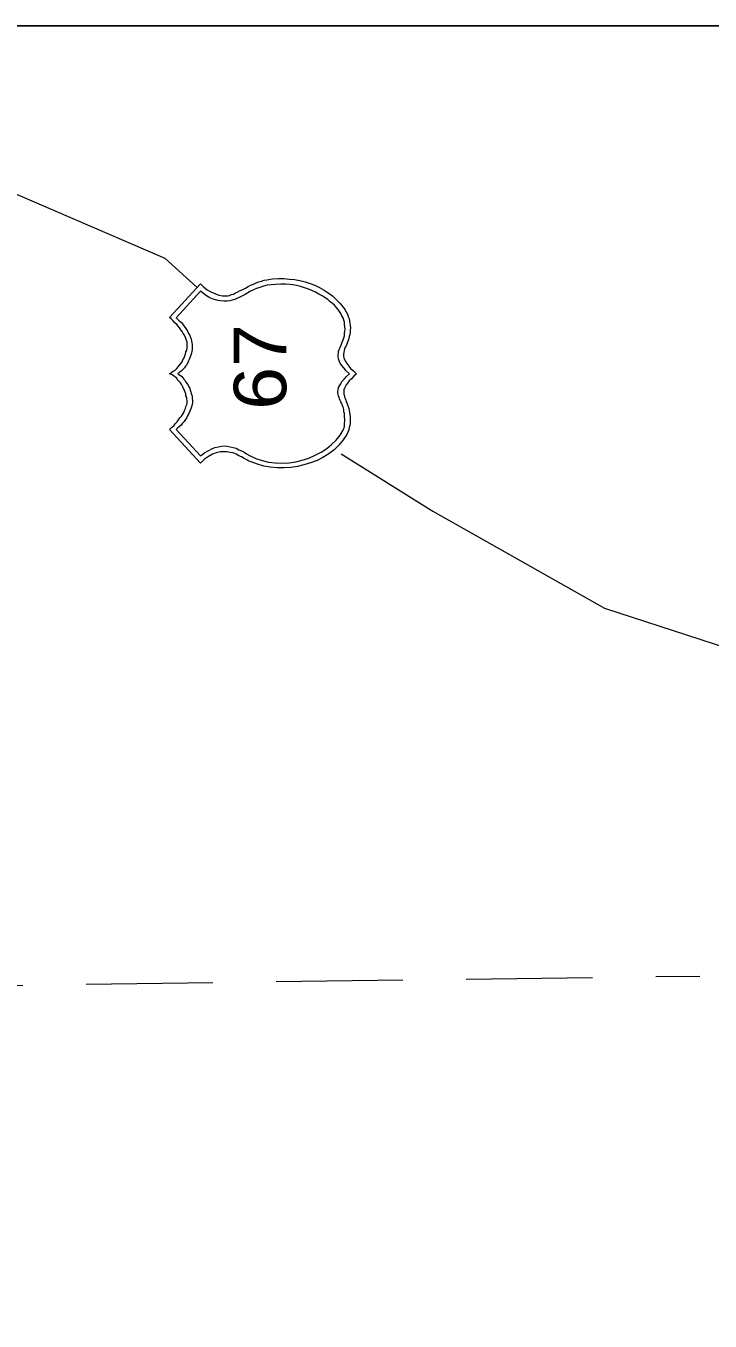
# Model space of a CAD drawing. Extents: x 2363323 to 2367082, y 6956018 to 6980837.
# Drawn here: x 2366064.3 to 2366130.8, y 6980709.7 to 6980835.5 of the extents above; entities that cross this region are included whole.
import ezdxf

# ---------------------------------------------------------------- set-up
doc = ezdxf.new("R2010")
doc.units = 0
doc.header["$LTSCALE"] = 4.1
doc.linetypes.add('MEDIUM_DASHED', pattern=[4.5, 3, -1.5])
doc.layers.add('62', color=7, linetype='Continuous', lineweight=13)
doc.layers.add('63', color=7, linetype='Continuous', lineweight=13)

msp = doc.modelspace()

# ---------------------------------------------------------------- linework, layer by layer
at = {"layer": '62'}
msp.add_line((2366077.847, 6980812.974), (2366080.974, 6980810.118), dxfattribs=at)
at = {"layer": '62', "linetype": 'MEDIUM_DASHED'}
msp.add_line((2365848.822, 6980739.484), (2366129.802, 6980743.218), dxfattribs=at)
at = {"layer": '62', "lineweight": 25}
msp.add_lwpolyline([(2365753.976, 6980385.954), (2366219.249, 6980385.954), (2366219.249, 6980835.546), (2365753.974, 6980835.546)], dxfattribs=at)
at = {"layer": '62'}
for points in [[(2366041.328, 6980835.544), (2366046.682, 6980830.731), (2366061.803, 6980819.864), (2366077.847, 6980812.974)], [(2366081.312, 6980793.062), (2366078.298, 6980796.326), (2366078.5, 6980796.506), (2366078.704, 6980796.686), (2366078.86, 6980796.888), (2366079.04, 6980797.066), (2366079.176, 6980797.25), (2366079.31, 6980797.45), (2366079.446, 6980797.608), (2366079.581, 6980797.81), (2366079.692, 6980797.99), (2366079.76, 6980798.172), (2366079.85, 6980798.373), (2366079.894, 6980798.553), (2366079.962, 6980798.756), (2366080.008, 6980798.913), (2366080.008, 6980799.117), (2366079.983, 6980799.318), (2366079.964, 6980799.452), (2366079.896, 6980799.61), (2366079.872, 6980799.79), (2366079.827, 6980799.97), (2366079.738, 6980800.152), (2366079.67, 6980800.308), (2366079.581, 6980800.488), (2366079.491, 6980800.668), (2366079.356, 6980800.848), (2366079.244, 6980801.006), (2366079.084, 6980801.163), (2366078.994, 6980801.32), (2366078.814, 6980801.456), (2366078.657, 6980801.568), (2366078.477, 6980801.658), (2366078.296, 6980801.748), (2366078.477, 6980801.86), (2366078.657, 6980801.997), (2366078.837, 6980802.108), (2366078.994, 6980802.266), (2366079.152, 6980802.4), (2366079.266, 6980802.58), (2366079.401, 6980802.738), (2366079.512, 6980802.918), (2366079.604, 6980803.098), (2366079.716, 6980803.278), (2366079.784, 6980803.48), (2366079.851, 6980803.66), (2366079.894, 6980803.886), (2366079.964, 6980804.043), (2366080.008, 6980804.268), (2366080.008, 6980804.47), (2366080.008, 6980804.628), (2366080.008, 6980804.808), (2366079.941, 6980804.964), (2366079.896, 6980805.168), (2366079.806, 6980805.326), (2366079.737, 6980805.506), (2366079.626, 6980805.663), (2366079.536, 6980805.843), (2366079.401, 6980806.002), (2366079.266, 6980806.204), (2366079.131, 6980806.36), (2366078.996, 6980806.542), (2366078.816, 6980806.698), (2366078.657, 6980806.9), (2366078.477, 6980807.037), (2366078.298, 6980807.216), (2366081.314, 6980810.478), (2366081.603, 6980810.186), (2366081.942, 6980809.893), (2366082.324, 6980809.69), (2366082.707, 6980809.533), (2366083.09, 6980809.377), (2366083.45, 6980809.33), (2366083.742, 6980809.31), (2366083.946, 6980809.33), (2366084.126, 6980809.354), (2366084.304, 6980809.443), (2366084.508, 6980809.488), (2366084.711, 6980809.6), (2366084.934, 6980809.712), (2366085.161, 6980809.827), (2366085.408, 6980809.938), (2366085.677, 6980810.073), (2366085.924, 6980810.21), (2366086.172, 6980810.344), (2366086.464, 6980810.456), (2366086.712, 6980810.568), (2366086.984, 6980810.68), (2366087.231, 6980810.748), (2366087.477, 6980810.84), (2366087.747, 6980810.862), (2366088.31, 6980810.952), (2366088.874, 6980810.997), (2366089.391, 6980810.996), (2366089.93, 6980810.95), (2366090.446, 6980810.904), (2366090.964, 6980810.793), (2366091.46, 6980810.68), (2366091.956, 6980810.523), (2366092.427, 6980810.343), (2366092.878, 6980810.12)], [(2366093.666, 6980808.948), (2366093.418, 6980809.126), (2366093.124, 6980809.33), (2366092.81, 6980809.488), (2366092.472, 6980809.67), (2366092.112, 6980809.824), (2366091.73, 6980809.983), (2366091.323, 6980810.14), (2366090.92, 6980810.253), (2366090.47, 6980810.343), (2366090.02, 6980810.41), (2366089.571, 6980810.456), (2366089.098, 6980810.456), (2366088.602, 6980810.433), (2366088.174, 6980810.388), (2366087.77, 6980810.342), (2366087.41, 6980810.253), (2366087.072, 6980810.139), (2366086.758, 6980810.028), (2366086.442, 6980809.893), (2366086.172, 6980809.76), (2366085.904, 6980809.6), (2366085.632, 6980809.443), (2366085.386, 6980809.33), (2366085.138, 6980809.196), (2366084.891, 6980809.083), (2366084.644, 6980808.972), (2366084.394, 6980808.903), (2366084.17, 6980808.836), (2366083.9, 6980808.79), (2366083.584, 6980808.789), (2366083.226, 6980808.834), (2366082.887, 6980808.903), (2366082.551, 6980808.992), (2366082.214, 6980809.128), (2366081.898, 6980809.33), (2366081.604, 6980809.534), (2366081.312, 6980809.756), (2366078.928, 6980807.193), (2366079.084, 6980807.036), (2366079.244, 6980806.9), (2366079.424, 6980806.743), (2366079.558, 6980806.587), (2366079.694, 6980806.406), (2366079.827, 6980806.226), (2366079.941, 6980806.047), (2366080.052, 6980805.866), (2366080.142, 6980805.663), (2366080.254, 6980805.483), (2366080.344, 6980805.28), (2366080.39, 6980805.123), (2366080.434, 6980804.922), (2366080.458, 6980804.763), (2366080.502, 6980804.628), (2366080.504, 6980804.47), (2366080.504, 6980804.312), (2366080.48, 6980804.11), (2366080.457, 6980803.932), (2366080.434, 6980803.75), (2366080.368, 6980803.546), (2366080.3, 6980803.39), (2366080.232, 6980803.188), (2366080.142, 6980803.008), (2366080.074, 6980802.85), (2366079.962, 6980802.626), (2366079.85, 6980802.49), (2366079.737, 6980802.333), (2366079.604, 6980802.153), (2366079.446, 6980802.04), (2366079.31, 6980801.883), (2366079.107, 6980801.75), (2366079.287, 6980801.613), (2366079.446, 6980801.502), (2366079.58, 6980801.343), (2366079.692, 6980801.208), (2366079.806, 6980801.072), (2366079.896, 6980800.938), (2366080.007, 6980800.76), (2366080.12, 6980800.647), (2366080.163, 6980800.466), (2366080.254, 6980800.31), (2366080.301, 6980800.15), (2366080.367, 6980799.993), (2366080.39, 6980799.836), (2366080.457, 6980799.656), (2366080.48, 6980799.5), (2366080.504, 6980799.34), (2366080.524, 6980799.16), (2366080.524, 6980798.936), (2366080.48, 6980798.757), (2366080.434, 6980798.53), (2366080.367, 6980798.328), (2366080.277, 6980798.102), (2366080.187, 6980797.88), (2366080.074, 6980797.72), (2366079.964, 6980797.496), (2366079.851, 6980797.293), (2366079.716, 6980797.113), (2366079.557, 6980796.956), (2366079.422, 6980796.754), (2366079.242, 6980796.596)], [(2366092.878, 6980810.12), (2366093.304, 6980809.87), (2366093.71, 6980809.6), (2366094.116, 6980809.31), (2366094.497, 6980808.95), (2366094.834, 6980808.588), (2366095.172, 6980808.206), (2366095.33, 6980807.98), (2366095.466, 6980807.756), (2366095.577, 6980807.53), (2366095.643, 6980807.306), (2366095.734, 6980807.103), (2366095.781, 6980806.878), (2366095.826, 6980806.63), (2366095.848, 6980806.43), (2366095.871, 6980806.203), (2366095.847, 6980805.978), (2366095.847, 6980805.777), (2366095.804, 6980805.574), (2366095.734, 6980805.35), (2366095.712, 6980805.168), (2366095.644, 6980804.99), (2366095.578, 6980804.808), (2366095.51, 6980804.628), (2366095.442, 6980804.47), (2366095.35, 6980804.313), (2366095.308, 6980804.154), (2366095.262, 6980803.998), (2366095.217, 6980803.818), (2366095.196, 6980803.659), (2366095.196, 6980803.48), (2366095.241, 6980803.299), (2366095.308, 6980803.12), (2366095.42, 6980802.918), (2366095.532, 6980802.738), (2366095.714, 6980802.49), (2366095.89, 6980802.266), (2366096.164, 6980802.04), (2366096.456, 6980801.748), (2366096.186, 6980801.5), (2366095.96, 6980801.253), (2366095.734, 6980801.052), (2366095.601, 6980800.848), (2366095.466, 6980800.668), (2366095.352, 6980800.488), (2366095.308, 6980800.33), (2366095.24, 6980800.173), (2366095.218, 6980800.036), (2366095.217, 6980799.88), (2366095.24, 6980799.766), (2366095.284, 6980799.61), (2366095.307, 6980799.476), (2366095.352, 6980799.34), (2366095.42, 6980799.183), (2366095.464, 6980799.026), (2366095.534, 6980798.913), (2366095.577, 6980798.733), (2366095.646, 6980798.553), (2366095.712, 6980798.374), (2366095.736, 6980798.17), (2366095.781, 6980797.992), (2366095.824, 6980797.766), (2366095.847, 6980797.586), (2366095.847, 6980797.36), (2366095.847, 6980797.18), (2366095.848, 6980796.956), (2366095.824, 6980796.708), (2366095.757, 6980796.506), (2366095.712, 6980796.28), (2366095.624, 6980796.056), (2366095.508, 6980795.83), (2366095.172, 6980795.314), (2366094.744, 6980794.816), (2366094.274, 6980794.366), (2366093.756, 6980793.962), (2366093.192, 6980793.602), (2366092.631, 6980793.31), (2366092.001, 6980793.084), (2366091.347, 6980792.882), (2366090.717, 6980792.746), (2366090.064, 6980792.632), (2366089.39, 6980792.589), (2366088.737, 6980792.589), (2366088.064, 6980792.655), (2366087.454, 6980792.769), (2366086.826, 6980792.949), (2366086.24, 6980793.174), (2366086.016, 6980793.262), (2366085.79, 6980793.376), (2366085.542, 6980793.512), (2366085.294, 6980793.669), (2366085.026, 6980793.782), (2366084.756, 6980793.916), (2366084.464, 6980794.053), (2366084.171, 6980794.096), (2366083.854, 6980794.164), (2366083.518, 6980794.164), (2366083.202, 6980794.164), (2366082.842, 6980794.052), (2366082.482, 6980793.938), (2366082.077, 6980793.714)], [(2366078.951, 6980796.327), (2366081.312, 6980793.759), (2366081.694, 6980794.052), (2366082.054, 6980794.254), (2366082.392, 6980794.434), (2366082.707, 6980794.569), (2366083.044, 6980794.638), (2366083.338, 6980794.704), (2366083.607, 6980794.749), (2366083.901, 6980794.706), (2366084.192, 6980794.638), (2366084.464, 6980794.592), (2366084.756, 6980794.502), (2366085.024, 6980794.366), (2366085.272, 6980794.256), (2366085.544, 6980794.119), (2366085.788, 6980793.962), (2366086.06, 6980793.806), (2366086.667, 6980793.512), (2366087.298, 6980793.309), (2366087.904, 6980793.152), (2366088.557, 6980793.084), (2366089.234, 6980793.062), (2366089.907, 6980793.084), (2366090.56, 6980793.196), (2366091.191, 6980793.354), (2366091.844, 6980793.556), (2366092.45, 6980793.826), (2366093.036, 6980794.119), (2366093.574, 6980794.479), (2366094.024, 6980794.863), (2366094.498, 6980795.29), (2366094.857, 6980795.762), (2366095.172, 6980796.258), (2366095.194, 6980796.37), (2366095.262, 6980796.484), (2366095.308, 6980796.64), (2366095.307, 6980796.822), (2366095.307, 6980796.956), (2366095.33, 6980797.137), (2366095.33, 6980797.316), (2366095.308, 6980797.496), (2366095.307, 6980797.698), (2366095.308, 6980797.878), (2366095.24, 6980798.058), (2366095.217, 6980798.238), (2366095.194, 6980798.418), (2366095.127, 6980798.576), (2366095.082, 6980798.734), (2366095.037, 6980798.868), (2366094.948, 6980799.026), (2366094.88, 6980799.16), (2366094.812, 6980799.296), (2366094.768, 6980799.43), (2366094.701, 6980799.61), (2366094.678, 6980799.723), (2366094.654, 6980799.88), (2366094.654, 6980800.038), (2366094.677, 6980800.197), (2366094.722, 6980800.42), (2366094.791, 6980800.578), (2366094.924, 6980800.76), (2366095.037, 6980800.983), (2366095.262, 6980801.21), (2366095.487, 6980801.478), (2366095.78, 6980801.726), (2366095.466, 6980802.04), (2366095.24, 6980802.312), (2366095.038, 6980802.537), (2366094.88, 6980802.783), (2366094.79, 6980803.01), (2366094.722, 6980803.188), (2366094.678, 6980803.39), (2366094.677, 6980803.593), (2366094.7, 6980803.773), (2366094.722, 6980803.932), (2366094.79, 6980804.11), (2366094.857, 6980804.292), (2366094.924, 6980804.47), (2366095.016, 6980804.628), (2366095.082, 6980804.829), (2366095.172, 6980805.033), (2366095.217, 6980805.236), (2366095.307, 6980805.438), (2366095.307, 6980805.664), (2366095.33, 6980805.866), (2366095.354, 6980806.09), (2366095.33, 6980806.316), (2366095.307, 6980806.518), (2366095.286, 6980806.743), (2366095.216, 6980806.944), (2366095.172, 6980807.172), (2366095.038, 6980807.374), (2366094.948, 6980807.598), (2366094.814, 6980807.78), (2366094.678, 6980808.003), (2366094.497, 6980808.206), (2366094.317, 6980808.408), (2366094.137, 6980808.564), (2366093.89, 6980808.746), (2366093.666, 6980808.948)], [(2366079.242, 6980796.596), (2366079.086, 6980796.46), (2366078.951, 6980796.327)], [(2366082.077, 6980793.714), (2366081.696, 6980793.444), (2366081.312, 6980793.062)], [(2366094.97, 6980793.962), (2366103.882, 6980788.406), (2366120.534, 6980778.952), (2366139.278, 6980772.878), (2366153.61, 6980769.728), (2366166.728, 6980753.031), (2366176.79, 6980752.894), (2366186.194, 6980736.56), (2366195.014, 6980723.396), (2366202.238, 6980707.329), (2366206.47, 6980684.916), (2366210.836, 6980665.836), (2366216.234, 6980645.043), (2366219.25, 6980632.51)]]:
    msp.add_lwpolyline(points, dxfattribs=at)
at = {"layer": '63'}
msp.add_line((2366077.847, 6980812.974), (2366080.974, 6980810.118), dxfattribs=at)
at = {"layer": '63', "linetype": 'MEDIUM_DASHED'}
msp.add_line((2365848.822, 6980739.484), (2366129.802, 6980743.218), dxfattribs=at)
at = {"layer": '63', "lineweight": 25}
msp.add_lwpolyline([(2365753.976, 6980385.954), (2366219.249, 6980385.954), (2366219.249, 6980835.546), (2365753.974, 6980835.546)], dxfattribs=at)
at = {"layer": '63'}
for points in [[(2366041.328, 6980835.544), (2366046.682, 6980830.731), (2366061.803, 6980819.864), (2366077.847, 6980812.974)], [(2366081.312, 6980793.062), (2366078.298, 6980796.326), (2366078.5, 6980796.506), (2366078.704, 6980796.686), (2366078.86, 6980796.888), (2366079.04, 6980797.066), (2366079.176, 6980797.25), (2366079.31, 6980797.45), (2366079.446, 6980797.608), (2366079.581, 6980797.81), (2366079.692, 6980797.99), (2366079.76, 6980798.172), (2366079.85, 6980798.373), (2366079.894, 6980798.553), (2366079.962, 6980798.756), (2366080.008, 6980798.913), (2366080.008, 6980799.117), (2366079.983, 6980799.318), (2366079.964, 6980799.452), (2366079.896, 6980799.61), (2366079.872, 6980799.79), (2366079.827, 6980799.97), (2366079.738, 6980800.152), (2366079.67, 6980800.308), (2366079.581, 6980800.488), (2366079.491, 6980800.668), (2366079.356, 6980800.848), (2366079.244, 6980801.006), (2366079.084, 6980801.163), (2366078.994, 6980801.32), (2366078.814, 6980801.456), (2366078.657, 6980801.568), (2366078.477, 6980801.658), (2366078.296, 6980801.748), (2366078.477, 6980801.86), (2366078.657, 6980801.997), (2366078.837, 6980802.108), (2366078.994, 6980802.266), (2366079.152, 6980802.4), (2366079.266, 6980802.58), (2366079.401, 6980802.738), (2366079.512, 6980802.918), (2366079.604, 6980803.098), (2366079.716, 6980803.278), (2366079.784, 6980803.48), (2366079.851, 6980803.66), (2366079.894, 6980803.886), (2366079.964, 6980804.043), (2366080.008, 6980804.268), (2366080.008, 6980804.47), (2366080.008, 6980804.628), (2366080.008, 6980804.808), (2366079.941, 6980804.964), (2366079.896, 6980805.168), (2366079.806, 6980805.326), (2366079.737, 6980805.506), (2366079.626, 6980805.663), (2366079.536, 6980805.843), (2366079.401, 6980806.002), (2366079.266, 6980806.204), (2366079.131, 6980806.36), (2366078.996, 6980806.542), (2366078.816, 6980806.698), (2366078.657, 6980806.9), (2366078.477, 6980807.037), (2366078.298, 6980807.216), (2366081.314, 6980810.478), (2366081.603, 6980810.186), (2366081.942, 6980809.893), (2366082.324, 6980809.69), (2366082.707, 6980809.533), (2366083.09, 6980809.377), (2366083.45, 6980809.33), (2366083.742, 6980809.31), (2366083.946, 6980809.33), (2366084.126, 6980809.354), (2366084.304, 6980809.443), (2366084.508, 6980809.488), (2366084.711, 6980809.6), (2366084.934, 6980809.712), (2366085.161, 6980809.827), (2366085.408, 6980809.938), (2366085.677, 6980810.073), (2366085.924, 6980810.21), (2366086.172, 6980810.344), (2366086.464, 6980810.456), (2366086.712, 6980810.568), (2366086.984, 6980810.68), (2366087.231, 6980810.748), (2366087.477, 6980810.84), (2366087.747, 6980810.862), (2366088.31, 6980810.952), (2366088.874, 6980810.997), (2366089.391, 6980810.996), (2366089.93, 6980810.95), (2366090.446, 6980810.904), (2366090.964, 6980810.793), (2366091.46, 6980810.68), (2366091.956, 6980810.523), (2366092.427, 6980810.343), (2366092.878, 6980810.12)], [(2366093.666, 6980808.948), (2366093.418, 6980809.126), (2366093.124, 6980809.33), (2366092.81, 6980809.488), (2366092.472, 6980809.67), (2366092.112, 6980809.824), (2366091.73, 6980809.983), (2366091.323, 6980810.14), (2366090.92, 6980810.253), (2366090.47, 6980810.343), (2366090.02, 6980810.41), (2366089.571, 6980810.456), (2366089.098, 6980810.456), (2366088.602, 6980810.433), (2366088.174, 6980810.388), (2366087.77, 6980810.342), (2366087.41, 6980810.253), (2366087.072, 6980810.139), (2366086.758, 6980810.028), (2366086.442, 6980809.893), (2366086.172, 6980809.76), (2366085.904, 6980809.6), (2366085.632, 6980809.443), (2366085.386, 6980809.33), (2366085.138, 6980809.196), (2366084.891, 6980809.083), (2366084.644, 6980808.972), (2366084.394, 6980808.903), (2366084.17, 6980808.836), (2366083.9, 6980808.79), (2366083.584, 6980808.789), (2366083.226, 6980808.834), (2366082.887, 6980808.903), (2366082.551, 6980808.992), (2366082.214, 6980809.128), (2366081.898, 6980809.33), (2366081.604, 6980809.534), (2366081.312, 6980809.756), (2366078.928, 6980807.193), (2366079.084, 6980807.036), (2366079.244, 6980806.9), (2366079.424, 6980806.743), (2366079.558, 6980806.587), (2366079.694, 6980806.406), (2366079.827, 6980806.226), (2366079.941, 6980806.047), (2366080.052, 6980805.866), (2366080.142, 6980805.663), (2366080.254, 6980805.483), (2366080.344, 6980805.28), (2366080.39, 6980805.123), (2366080.434, 6980804.922), (2366080.458, 6980804.763), (2366080.502, 6980804.628), (2366080.504, 6980804.47), (2366080.504, 6980804.312), (2366080.48, 6980804.11), (2366080.457, 6980803.932), (2366080.434, 6980803.75), (2366080.368, 6980803.546), (2366080.3, 6980803.39), (2366080.232, 6980803.188), (2366080.142, 6980803.008), (2366080.074, 6980802.85), (2366079.962, 6980802.626), (2366079.85, 6980802.49), (2366079.737, 6980802.333), (2366079.604, 6980802.153), (2366079.446, 6980802.04), (2366079.31, 6980801.883), (2366079.107, 6980801.75), (2366079.287, 6980801.613), (2366079.446, 6980801.502), (2366079.58, 6980801.343), (2366079.692, 6980801.208), (2366079.806, 6980801.072), (2366079.896, 6980800.938), (2366080.007, 6980800.76), (2366080.12, 6980800.647), (2366080.163, 6980800.466), (2366080.254, 6980800.31), (2366080.301, 6980800.15), (2366080.367, 6980799.993), (2366080.39, 6980799.836), (2366080.457, 6980799.656), (2366080.48, 6980799.5), (2366080.504, 6980799.34), (2366080.524, 6980799.16), (2366080.524, 6980798.936), (2366080.48, 6980798.757), (2366080.434, 6980798.53), (2366080.367, 6980798.328), (2366080.277, 6980798.102), (2366080.187, 6980797.88), (2366080.074, 6980797.72), (2366079.964, 6980797.496), (2366079.851, 6980797.293), (2366079.716, 6980797.113), (2366079.557, 6980796.956), (2366079.422, 6980796.754), (2366079.242, 6980796.596)], [(2366092.878, 6980810.12), (2366093.304, 6980809.87), (2366093.71, 6980809.6), (2366094.116, 6980809.31), (2366094.497, 6980808.95), (2366094.834, 6980808.588), (2366095.172, 6980808.206), (2366095.33, 6980807.98), (2366095.466, 6980807.756), (2366095.577, 6980807.53), (2366095.643, 6980807.306), (2366095.734, 6980807.103), (2366095.781, 6980806.878), (2366095.826, 6980806.63), (2366095.848, 6980806.43), (2366095.871, 6980806.203), (2366095.847, 6980805.978), (2366095.847, 6980805.777), (2366095.804, 6980805.574), (2366095.734, 6980805.35), (2366095.712, 6980805.168), (2366095.644, 6980804.99), (2366095.578, 6980804.808), (2366095.51, 6980804.628), (2366095.442, 6980804.47), (2366095.35, 6980804.313), (2366095.308, 6980804.154), (2366095.262, 6980803.998), (2366095.217, 6980803.818), (2366095.196, 6980803.659), (2366095.196, 6980803.48), (2366095.241, 6980803.299), (2366095.308, 6980803.12), (2366095.42, 6980802.918), (2366095.532, 6980802.738), (2366095.714, 6980802.49), (2366095.89, 6980802.266), (2366096.164, 6980802.04), (2366096.456, 6980801.748), (2366096.186, 6980801.5), (2366095.96, 6980801.253), (2366095.734, 6980801.052), (2366095.601, 6980800.848), (2366095.466, 6980800.668), (2366095.352, 6980800.488), (2366095.308, 6980800.33), (2366095.24, 6980800.173), (2366095.218, 6980800.036), (2366095.217, 6980799.88), (2366095.24, 6980799.766), (2366095.284, 6980799.61), (2366095.307, 6980799.476), (2366095.352, 6980799.34), (2366095.42, 6980799.183), (2366095.464, 6980799.026), (2366095.534, 6980798.913), (2366095.577, 6980798.733), (2366095.646, 6980798.553), (2366095.712, 6980798.374), (2366095.736, 6980798.17), (2366095.781, 6980797.992), (2366095.824, 6980797.766), (2366095.847, 6980797.586), (2366095.847, 6980797.36), (2366095.847, 6980797.18), (2366095.848, 6980796.956), (2366095.824, 6980796.708), (2366095.757, 6980796.506), (2366095.712, 6980796.28), (2366095.624, 6980796.056), (2366095.508, 6980795.83), (2366095.172, 6980795.314), (2366094.744, 6980794.816), (2366094.274, 6980794.366), (2366093.756, 6980793.962), (2366093.192, 6980793.602), (2366092.631, 6980793.31), (2366092.001, 6980793.084), (2366091.347, 6980792.882), (2366090.717, 6980792.746), (2366090.064, 6980792.632), (2366089.39, 6980792.589), (2366088.737, 6980792.589), (2366088.064, 6980792.655), (2366087.454, 6980792.769), (2366086.826, 6980792.949), (2366086.24, 6980793.174), (2366086.016, 6980793.262), (2366085.79, 6980793.376), (2366085.542, 6980793.512), (2366085.294, 6980793.669), (2366085.026, 6980793.782), (2366084.756, 6980793.916), (2366084.464, 6980794.053), (2366084.171, 6980794.096), (2366083.854, 6980794.164), (2366083.518, 6980794.164), (2366083.202, 6980794.164), (2366082.842, 6980794.052), (2366082.482, 6980793.938), (2366082.077, 6980793.714)], [(2366078.951, 6980796.327), (2366081.312, 6980793.759), (2366081.694, 6980794.052), (2366082.054, 6980794.254), (2366082.392, 6980794.434), (2366082.707, 6980794.569), (2366083.044, 6980794.638), (2366083.338, 6980794.704), (2366083.607, 6980794.749), (2366083.901, 6980794.706), (2366084.192, 6980794.638), (2366084.464, 6980794.592), (2366084.756, 6980794.502), (2366085.024, 6980794.366), (2366085.272, 6980794.256), (2366085.544, 6980794.119), (2366085.788, 6980793.962), (2366086.06, 6980793.806), (2366086.667, 6980793.512), (2366087.298, 6980793.309), (2366087.904, 6980793.152), (2366088.557, 6980793.084), (2366089.234, 6980793.062), (2366089.907, 6980793.084), (2366090.56, 6980793.196), (2366091.191, 6980793.354), (2366091.844, 6980793.556), (2366092.45, 6980793.826), (2366093.036, 6980794.119), (2366093.574, 6980794.479), (2366094.024, 6980794.863), (2366094.498, 6980795.29), (2366094.857, 6980795.762), (2366095.172, 6980796.258), (2366095.194, 6980796.37), (2366095.262, 6980796.484), (2366095.308, 6980796.64), (2366095.307, 6980796.822), (2366095.307, 6980796.956), (2366095.33, 6980797.137), (2366095.33, 6980797.316), (2366095.308, 6980797.496), (2366095.307, 6980797.698), (2366095.308, 6980797.878), (2366095.24, 6980798.058), (2366095.217, 6980798.238), (2366095.194, 6980798.418), (2366095.127, 6980798.576), (2366095.082, 6980798.734), (2366095.037, 6980798.868), (2366094.948, 6980799.026), (2366094.88, 6980799.16), (2366094.812, 6980799.296), (2366094.768, 6980799.43), (2366094.701, 6980799.61), (2366094.678, 6980799.723), (2366094.654, 6980799.88), (2366094.654, 6980800.038), (2366094.677, 6980800.197), (2366094.722, 6980800.42), (2366094.791, 6980800.578), (2366094.924, 6980800.76), (2366095.037, 6980800.983), (2366095.262, 6980801.21), (2366095.487, 6980801.478), (2366095.78, 6980801.726), (2366095.466, 6980802.04), (2366095.24, 6980802.312), (2366095.038, 6980802.537), (2366094.88, 6980802.783), (2366094.79, 6980803.01), (2366094.722, 6980803.188), (2366094.678, 6980803.39), (2366094.677, 6980803.593), (2366094.7, 6980803.773), (2366094.722, 6980803.932), (2366094.79, 6980804.11), (2366094.857, 6980804.292), (2366094.924, 6980804.47), (2366095.016, 6980804.628), (2366095.082, 6980804.829), (2366095.172, 6980805.033), (2366095.217, 6980805.236), (2366095.307, 6980805.438), (2366095.307, 6980805.664), (2366095.33, 6980805.866), (2366095.354, 6980806.09), (2366095.33, 6980806.316), (2366095.307, 6980806.518), (2366095.286, 6980806.743), (2366095.216, 6980806.944), (2366095.172, 6980807.172), (2366095.038, 6980807.374), (2366094.948, 6980807.598), (2366094.814, 6980807.78), (2366094.678, 6980808.003), (2366094.497, 6980808.206), (2366094.317, 6980808.408), (2366094.137, 6980808.564), (2366093.89, 6980808.746), (2366093.666, 6980808.948)], [(2366079.242, 6980796.596), (2366079.086, 6980796.46), (2366078.951, 6980796.327)], [(2366082.077, 6980793.714), (2366081.696, 6980793.444), (2366081.312, 6980793.062)], [(2366094.97, 6980793.962), (2366103.882, 6980788.406), (2366120.534, 6980778.952), (2366139.278, 6980772.878), (2366153.61, 6980769.728), (2366166.728, 6980753.031), (2366176.79, 6980752.894), (2366186.194, 6980736.56), (2366195.014, 6980723.396), (2366202.238, 6980707.329), (2366206.47, 6980684.916), (2366210.836, 6980665.836), (2366216.234, 6980645.043), (2366219.25, 6980632.51)]]:
    msp.add_lwpolyline(points, dxfattribs=at)

# ---------------------------------------------------------------- texts
at = {"layer": '62', "width": 1.1}
msp.add_text('67', height=5.099, rotation=90, dxfattribs=at).set_placement((2366089.636, 6980798.238))
at = {"layer": '63', "width": 1.1}
msp.add_text('67', height=5.099, rotation=90, dxfattribs=at).set_placement((2366089.636, 6980798.238))

doc.saveas('drawing.dxf')
